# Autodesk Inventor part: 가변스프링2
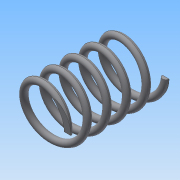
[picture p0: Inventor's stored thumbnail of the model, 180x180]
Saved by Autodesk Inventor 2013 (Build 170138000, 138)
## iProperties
Created: 2018-10
Part Number: 가변스프링2
Material: 일반
Document SubType Name: Modeling
Designer: Administrator
Density: 1 g/cm^3
Mass: 0.778124 g
Surface Area: 15.7881 cm^2
Volume: 0.778124 cm^3
Author: Administrator
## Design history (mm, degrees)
sketch "스케치1"
  geometry: L1 (0, 0)-(8, 0); L2 (0, 0)-(0, 29.48); L3 (0, 29.48)-(8, 29.48); C1 r 1 at (8, 0)
  constraints: 6 end point, 2 perpendicular, 1 centre point, 1 coincident, 1 horizontal
  dimensions: "d0" = 8 distance of L1.start L1.end; "d1" = 29.4802 distance of L1.start L2.end (derived); "d2" = 8 distance of L2.end L3.end; "d3" = 2 diameter of C1
feature "코일1" sketch "스케치1" pitch "d4" = 10; turns "d6" = 5; dims "d5" = 29.4802 (= d1), "d7" = 0, angle "d8" = 90 deg, angle "d9" = 90 deg, "d10" = 0, "d11" = 0
sketch "스케치2"
  geometry: L1 (29.48, 9.5)-(0, 9.5); L2 (0, 9.5)-(0, -9.5); L3 (0, -9.5)-(29.48, -9.5); L4 (29.48, -9.5)-(29.48, 9.5); 2 further points
  constraints: 8 end point, 2 parallel, 1 coincident, 1 horizontal, 1 midpoint, 1 perpendicular
  dimensions: "d12" = 29.4802 distance from line of point (0, 0) L4 (derived); "d13" = 19 distance between parallel lines of L3 L1
extrude "돌출1" sketch "스케치2" stored distance "d14" = 0; taper "d15" = 0 deg
node "솔리드1"
